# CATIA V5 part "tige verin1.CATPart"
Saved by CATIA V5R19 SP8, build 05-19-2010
Part number: tige verin1
Bounding box of the stored display mesh (mm): x 21.312 to 50, y -3 to 3, z 21.312 to 50
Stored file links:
  G:\EU_thinkMotion\CFAO_2010\MMS_groupe1\MMS_groupe1\A reprendre\OK\glenerrant\glenerrant\glenerrant\tige verin1.CATPart
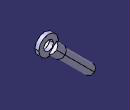
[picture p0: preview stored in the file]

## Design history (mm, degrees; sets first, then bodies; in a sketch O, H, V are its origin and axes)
Set1
  Point1: (45, 0, 45)
  Point2: (0, 0, 0)
  Line1: type PtPt, FirstPoint Point2, SecondPoint Point1
  Plane1: type Normal, Curve Line1, RefPoint Point1
Body1 (main body)
  Sketch1 on zx-plane, origin (0, 0, 0), H (-1, 0, 0), V (0, 0, 1)
    circle A1 centre (-45, 45) radius 2.5
    point P1 (-45, 45)
    circle A2 centre (-45, 45) radius 5
    point P2 (-45, 45)
    reference projected point E1 (-45, 45) from Point1
    reference projected point E2 (-45, 45) from Point1
    radius A2 = 5
    radius A1 = 2.5
    coincidence: E1 P2, P1 E2
  Pad1: profile Sketch1, direction (0, 1, 0), length 1, opposite side length 1
  Sketch2 on Plane1, origin (45, 0, 45), H (0, 1, 0), V (-0.7071, 0, 0.7071)
    circle A1 centre (0, 0) radius 3
    point P1 (0, 0)
    reference projected point E1 (0, 0) from Point1
    radius A1 = 3
    coincidence: E1 P1
  Pad2: profile Sketch2, direction (-0.7071, 0, -0.7071), length 9, opposite side length -3
  Sketch3 on end face of Pad2, origin (38.636, 0, 38.636), H (0, -1, 0), V (-0.7071, 0, 0.7071)
    circle A1 centre (0, 0) radius 2.5
    point P1 (0, 0)
    reference projected point E1 (0, 0) from Point1
    radius A1 = 2.5
    coincidence: P1 E1
  Pad3: profile Sketch3, direction (-0.7071, 0, -0.7071), length 22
